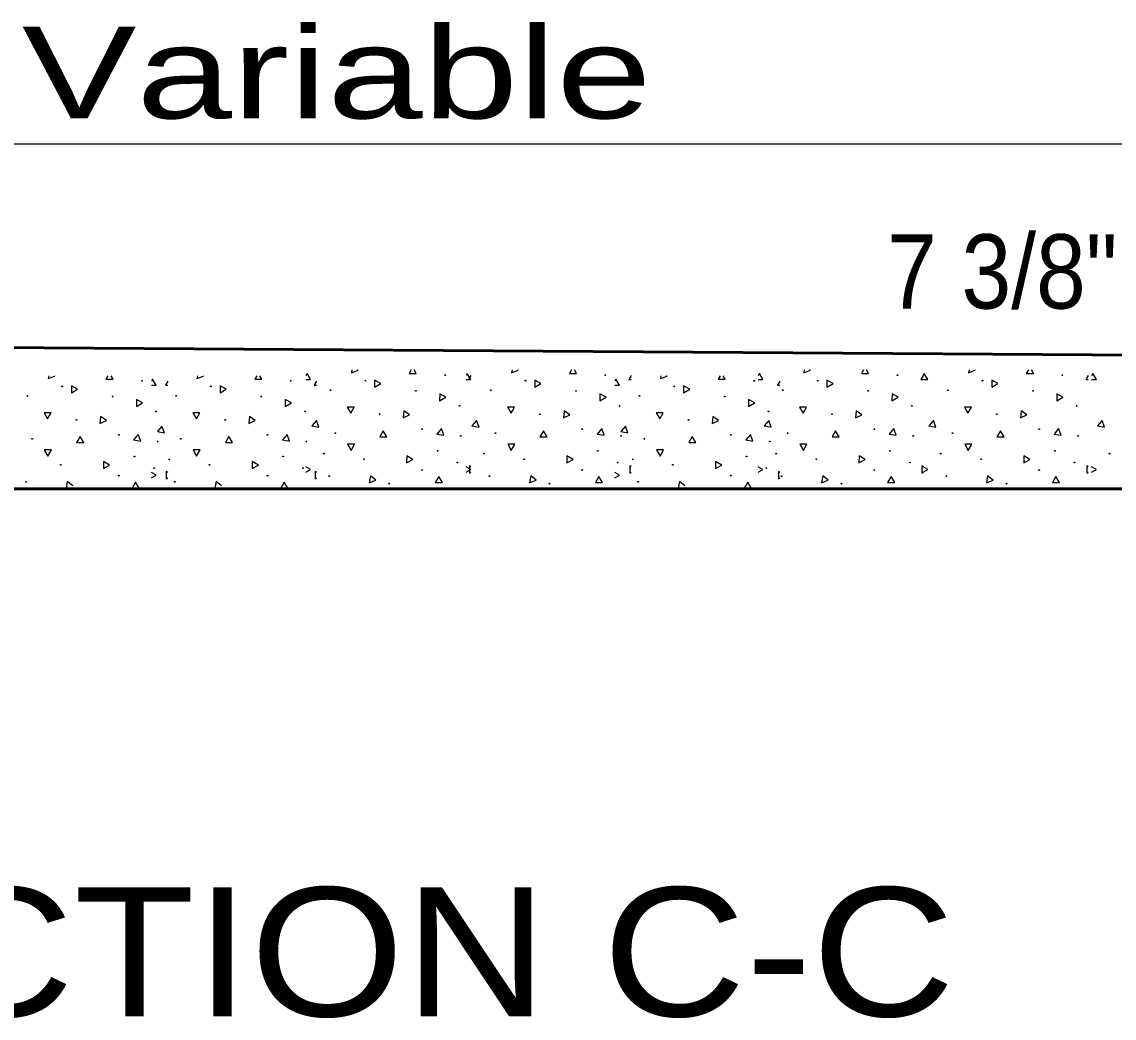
# Model space of a CAD drawing. Extents: x 75.6 to 110.9, y 28 to 50.
# Drawn here: x 100.105 to 101.892, y 35.466 to 37.097 of the extents above; entities that cross this region are included whole.
import ezdxf
from ezdxf.enums import TextEntityAlignment as Align

# ---------------------------------------------------------------- set-up
doc = ezdxf.new("R2010")
doc.units = 0
doc.header["$LTSCALE"] = 0.06
doc.layers.add('1', color=7, linetype='Continuous', lineweight=25)
doc.layers.add('3', color=7, linetype='Continuous', lineweight=13)

msp = doc.modelspace()

# ---------------------------------------------------------------- linework, layer by layer
at = {"layer": '1', "lineweight": 53}
for p, q in [((102.10992, 36.55025), (98.82217, 36.57225)), ((102.13775, 36.33233), (98.82217, 36.33233))]:
    msp.add_line(p, q, dxfattribs=at)
at = {"layer": '1'}
for p, q in [((100.64508, 36.527), (100.64433, 36.52242)), ((100.64433, 36.52242), (100.65525, 36.52642)), ((100.65525, 36.52642), (100.6545, 36.527)), ((100.74208, 36.527), (100.73875, 36.52125)), ((100.75042, 36.52125), (100.74708, 36.527)), ((100.90717, 36.527), (100.90642, 36.52242)), ((100.90642, 36.52242), (100.91733, 36.52642)), ((100.91733, 36.52642), (100.91658, 36.527)), ((101.00417, 36.527), (101.00083, 36.52125)), ((101.0125, 36.52125), (101.00917, 36.527)), ((101.38508, 36.527), (101.38433, 36.52242)), ((101.38433, 36.52242), (101.39525, 36.52642)), ((101.39525, 36.52642), (101.3945, 36.527)), ((101.48208, 36.527), (101.47875, 36.52125)), ((101.49042, 36.52125), (101.48708, 36.527)), ((101.65475, 36.527), (101.654, 36.52242)), ((101.654, 36.52242), (101.66492, 36.52642)), ((101.66492, 36.52642), (101.66417, 36.527)), ((101.75175, 36.527), (101.74842, 36.52125)), ((101.76008, 36.52125), (101.75675, 36.527)), ((100.14908, 36.51767), (100.14833, 36.51308)), ((100.14833, 36.51308), (100.15925, 36.51708)), ((100.15925, 36.51708), (100.1585, 36.51767)), ((100.24608, 36.51767), (100.24275, 36.51192)), ((100.24275, 36.51192), (100.25442, 36.51192)), ((100.25442, 36.51192), (100.25108, 36.51767)), ((100.31908, 36.51208), (100.31717, 36.50883)), ((100.32483, 36.502), (100.31908, 36.51208)), ((100.34383, 36.50883), (100.33992, 36.502)), ((100.39242, 36.51767), (100.39167, 36.51308)), ((100.39167, 36.51308), (100.40258, 36.51708)), ((100.40258, 36.51708), (100.40183, 36.51767)), ((100.48942, 36.51767), (100.48608, 36.51192)), ((100.48608, 36.51192), (100.49775, 36.51192)), ((100.49775, 36.51192), (100.49442, 36.51767)), ((100.57175, 36.52142), (100.56983, 36.51817)), ((100.56983, 36.51133), (100.5775, 36.51133)), ((100.5775, 36.51133), (100.57175, 36.52142)), ((100.58717, 36.50883), (100.58325, 36.502)), ((100.73875, 36.52125), (100.75042, 36.52125)), ((100.83383, 36.52142), (100.83192, 36.51817)), ((100.83192, 36.51133), (100.83958, 36.51133)), ((100.83958, 36.51133), (100.83383, 36.52142)), ((100.83983, 36.51817), (100.83592, 36.51133)), ((100.83592, 36.51133), (100.83983, 36.51133)), ((101.00083, 36.52125), (101.0125, 36.52125)), ((101.07717, 36.51208), (101.07525, 36.50883)), ((101.08292, 36.502), (101.07717, 36.51208)), ((101.10192, 36.51817), (101.098, 36.51133)), ((101.098, 36.51133), (101.10192, 36.51133)), ((101.1505, 36.51767), (101.14975, 36.51308)), ((101.14975, 36.51308), (101.16067, 36.51708)), ((101.16067, 36.51708), (101.15992, 36.51767)), ((101.2475, 36.51767), (101.24417, 36.51192)), ((101.24417, 36.51192), (101.25583, 36.51192)), ((101.25583, 36.51192), (101.2525, 36.51767)), ((101.31175, 36.52142), (101.30983, 36.51817)), ((101.30983, 36.51133), (101.3175, 36.51133)), ((101.3175, 36.51133), (101.31175, 36.52142)), ((101.34525, 36.50883), (101.34133, 36.502)), ((101.47875, 36.52125), (101.49042, 36.52125)), ((101.57983, 36.51817), (101.57592, 36.51133)), ((101.57592, 36.51133), (101.57983, 36.51133)), ((101.58142, 36.52142), (101.5795, 36.51817)), ((101.5795, 36.51133), (101.58717, 36.51133)), ((101.58717, 36.51133), (101.58142, 36.52142)), ((101.74842, 36.52125), (101.76008, 36.52125)), ((101.8495, 36.51817), (101.84558, 36.51133)), ((101.84558, 36.51133), (101.8495, 36.51133)), ((101.85725, 36.52142), (101.85533, 36.51817)), ((101.85533, 36.51133), (101.863, 36.51133)), ((101.863, 36.51133), (101.85725, 36.52142)), ((100.31717, 36.502), (100.32483, 36.502)), ((100.33992, 36.502), (100.34383, 36.502)), ((100.58325, 36.502), (100.58717, 36.502)), ((101.07525, 36.502), (101.08292, 36.502)), ((101.34133, 36.502), (101.34525, 36.502)), ((100.8375, 36.37), (100.8375, 36.35833)), ((100.8375, 36.37), (100.8375, 36.35833)), ((100.83983, 36.36867), (100.8375, 36.37)), ((100.83983, 36.36867), (100.8375, 36.37)), ((101.09958, 36.37), (101.09958, 36.35833)), ((101.09958, 36.37), (101.09958, 36.35833)), ((101.10192, 36.36867), (101.09958, 36.37)), ((101.10192, 36.36867), (101.09958, 36.37)), ((101.5775, 36.37), (101.5775, 36.35833)), ((101.5775, 36.37), (101.5775, 36.35833)), ((101.57983, 36.36867), (101.5775, 36.37)), ((101.57983, 36.36867), (101.5775, 36.37)), ((101.84717, 36.37), (101.84717, 36.35833)), ((101.84717, 36.37), (101.84717, 36.35833)), ((101.8495, 36.36867), (101.84717, 36.37)), ((101.8495, 36.36867), (101.84717, 36.37)), ((100.3415, 36.36067), (100.3415, 36.349)), ((100.3415, 36.36067), (100.3415, 36.349)), ((100.34383, 36.35933), (100.3415, 36.36067)), ((100.34383, 36.35933), (100.3415, 36.36067)), ((100.3415, 36.349), (100.34383, 36.35033)), ((100.3415, 36.349), (100.34383, 36.35033)), ((100.58483, 36.36067), (100.58483, 36.349)), ((100.58483, 36.36067), (100.58483, 36.349)), ((100.58717, 36.35933), (100.58483, 36.36067)), ((100.58717, 36.35933), (100.58483, 36.36067)), ((100.58483, 36.349), (100.58717, 36.35033)), ((100.58483, 36.349), (100.58717, 36.35033)), ((100.8375, 36.35833), (100.83983, 36.35967)), ((100.8375, 36.35833), (100.83983, 36.35967)), ((101.09958, 36.35833), (101.10192, 36.35967)), ((101.09958, 36.35833), (101.10192, 36.35967)), ((101.34292, 36.36067), (101.34292, 36.349)), ((101.34292, 36.36067), (101.34292, 36.349)), ((101.34525, 36.35933), (101.34292, 36.36067)), ((101.34525, 36.35933), (101.34292, 36.36067)), ((101.34292, 36.349), (101.34525, 36.35033)), ((101.34292, 36.349), (101.34525, 36.35033)), ((101.5775, 36.35833), (101.57983, 36.35967)), ((101.5775, 36.35833), (101.57983, 36.35967)), ((101.84717, 36.35833), (101.8495, 36.35967)), ((101.84717, 36.35833), (101.8495, 36.35967))]:
    msp.add_line(p, q, dxfattribs=at)
for points in [[(100.68225, 36.49875), (100.69233, 36.50467), (100.68233, 36.5105)], [(100.94433, 36.49875), (100.95442, 36.50467), (100.94442, 36.5105)], [(101.42225, 36.49875), (101.43233, 36.50467), (101.42233, 36.5105)], [(101.69192, 36.49875), (101.702, 36.50467), (101.692, 36.5105)], [(100.18625, 36.48942), (100.19633, 36.49533), (100.18633, 36.50117)], [(100.42958, 36.48942), (100.43967, 36.49533), (100.42967, 36.50117)], [(101.18767, 36.48942), (101.19775, 36.49533), (101.18775, 36.50117)], [(100.29258, 36.46717), (100.30275, 36.473), (100.29275, 36.47883)], [(100.53592, 36.46717), (100.54608, 36.473), (100.53608, 36.47883)], [(100.78858, 36.4765), (100.79875, 36.48233), (100.78875, 36.48817)], [(101.05067, 36.4765), (101.06083, 36.48233), (101.05083, 36.48817)], [(101.294, 36.46717), (101.30417, 36.473), (101.29417, 36.47883)], [(101.52858, 36.4765), (101.53875, 36.48233), (101.52875, 36.48817)], [(101.79825, 36.4765), (101.80842, 36.48233), (101.79842, 36.48817)], [(100.14733, 36.447), (100.15308, 36.457), (100.1415, 36.457)], [(100.39067, 36.447), (100.39642, 36.457), (100.38483, 36.457)], [(100.64333, 36.45633), (100.64908, 36.46633), (100.6375, 36.46633)], [(100.729, 36.44867), (100.7395, 36.45367), (100.73008, 36.46033)], [(100.90542, 36.45633), (100.91117, 36.46633), (100.89958, 36.46633)], [(100.99108, 36.44867), (101.00158, 36.45367), (100.99217, 36.46033)], [(101.14875, 36.447), (101.1545, 36.457), (101.14292, 36.457)], [(101.38333, 36.45633), (101.38908, 36.46633), (101.3775, 36.46633)], [(101.469, 36.44867), (101.4795, 36.45367), (101.47008, 36.46033)], [(101.653, 36.45633), (101.65875, 36.46633), (101.64717, 36.46633)], [(101.73867, 36.44867), (101.74917, 36.45367), (101.73975, 36.46033)], [(100.233, 36.43933), (100.2435, 36.44433), (100.23408, 36.451)], [(100.47633, 36.43933), (100.48683, 36.44433), (100.47742, 36.451)], [(100.5795, 36.4355), (100.591, 36.4335), (100.58708, 36.44433)], [(100.84158, 36.4355), (100.85308, 36.4335), (100.84917, 36.44433)], [(101.23442, 36.43933), (101.24492, 36.44433), (101.2355, 36.451)], [(101.3195, 36.4355), (101.331, 36.4335), (101.32708, 36.44433)], [(101.58917, 36.4355), (101.60067, 36.4335), (101.59675, 36.44433)], [(101.865, 36.4355), (101.8765, 36.4335), (101.87258, 36.44433)], [(100.19475, 36.40808), (100.20633, 36.40808), (100.2005, 36.41817)], [(100.28808, 36.41275), (100.29958, 36.41075), (100.29567, 36.42167)], [(100.32683, 36.42617), (100.33833, 36.42417), (100.33442, 36.435)], [(100.43808, 36.40808), (100.44967, 36.40808), (100.44383, 36.41817)], [(100.53142, 36.41275), (100.54292, 36.41075), (100.539, 36.42167)], [(100.69075, 36.41742), (100.70233, 36.41742), (100.6965, 36.4275)], [(100.78408, 36.42208), (100.79558, 36.42008), (100.79167, 36.431)], [(100.95283, 36.41742), (100.96442, 36.41742), (100.95858, 36.4275)], [(101.04617, 36.42208), (101.05767, 36.42008), (101.05375, 36.431)], [(101.08492, 36.42617), (101.09642, 36.42417), (101.0925, 36.435)], [(101.19617, 36.40808), (101.20775, 36.40808), (101.20192, 36.41817)], [(101.2895, 36.41275), (101.301, 36.41075), (101.29708, 36.42167)], [(101.43075, 36.41742), (101.44233, 36.41742), (101.4365, 36.4275)], [(101.52408, 36.42208), (101.53558, 36.42008), (101.53167, 36.431)], [(101.70042, 36.41742), (101.712, 36.41742), (101.70617, 36.4275)], [(101.79375, 36.42208), (101.80525, 36.42008), (101.80133, 36.431)], [(100.64375, 36.39542), (100.64958, 36.4055), (100.63792, 36.4055)], [(100.90583, 36.39542), (100.91167, 36.4055), (100.9, 36.4055)], [(101.38375, 36.39542), (101.38958, 36.4055), (101.37792, 36.4055)], [(101.65342, 36.39542), (101.65925, 36.4055), (101.64758, 36.4055)], [(100.14775, 36.38608), (100.15358, 36.39617), (100.14192, 36.39617)], [(100.39108, 36.38608), (100.39692, 36.39617), (100.38525, 36.39617)], [(100.73467, 36.37492), (100.74475, 36.38067), (100.73475, 36.3865)], [(100.99675, 36.37492), (101.00683, 36.38067), (100.99683, 36.3865)], [(101.14917, 36.38608), (101.155, 36.39617), (101.14333, 36.39617)], [(101.47467, 36.37492), (101.48475, 36.38067), (101.47475, 36.3865)], [(101.74433, 36.37492), (101.75442, 36.38067), (101.74442, 36.3865)], [(100.23867, 36.36558), (100.24875, 36.37133), (100.23875, 36.37717)], [(100.482, 36.36558), (100.49208, 36.37133), (100.48208, 36.37717)], [(101.24008, 36.36558), (101.25017, 36.37133), (101.24017, 36.37717)], [(100.6735, 36.3425), (100.68442, 36.3465), (100.6755, 36.354)], [(100.78142, 36.34283), (100.79308, 36.34283), (100.78725, 36.35292)], [(100.93558, 36.3425), (100.9465, 36.3465), (100.93758, 36.354)], [(101.0435, 36.34283), (101.05517, 36.34283), (101.04933, 36.35292)], [(101.4135, 36.3425), (101.42442, 36.3465), (101.4155, 36.354)], [(101.52142, 36.34283), (101.53308, 36.34283), (101.52725, 36.35292)], [(101.68317, 36.3425), (101.69408, 36.3465), (101.68517, 36.354)], [(101.79108, 36.34283), (101.80275, 36.34283), (101.79692, 36.35292)]]:
    msp.add_lwpolyline(points, close=True, dxfattribs=at)
for points in [[(100.56983, 36.35967), (100.57758, 36.36417), (100.56983, 36.36867)], [(100.83192, 36.35967), (100.83967, 36.36417), (100.83192, 36.36867)], [(101.30983, 36.35967), (101.31758, 36.36417), (101.30983, 36.36867)], [(101.5795, 36.35967), (101.58725, 36.36417), (101.5795, 36.36867)], [(101.85533, 36.35967), (101.86308, 36.36417), (101.85533, 36.36867)], [(100.31717, 36.35033), (100.32492, 36.35483), (100.31717, 36.35933)], [(101.07525, 36.35033), (101.083, 36.35483), (101.07525, 36.35933)], [(100.18842, 36.33717), (100.1795, 36.34467), (100.1775, 36.33317)], [(100.29708, 36.3335), (100.29125, 36.34358), (100.28542, 36.3335)], [(100.43175, 36.33717), (100.42283, 36.34467), (100.42083, 36.33317)], [(100.54042, 36.3335), (100.53458, 36.34358), (100.52875, 36.3335)], [(101.18983, 36.33717), (101.18092, 36.34467), (101.17892, 36.33317)], [(101.2985, 36.3335), (101.29267, 36.34358), (101.28683, 36.3335)]]:
    msp.add_lwpolyline(points, dxfattribs=at)
for centre in [(100.30165, 36.50908), (100.54498, 36.50908), (100.66712, 36.50948), (100.79765, 36.51842), (100.92921, 36.50948), (101.05973, 36.51842), (101.30306, 36.50908), (101.40712, 36.50948), (101.53765, 36.51842), (101.67679, 36.50948), (101.80731, 36.51842), (100.17112, 36.50015), (100.41446, 36.50015), (100.61022, 36.49387), (100.74968, 36.49277), (100.8723, 36.49387), (101.01176, 36.49277), (101.17254, 36.50015), (101.35022, 36.49387), (101.48968, 36.49277), (101.61989, 36.49387), (101.75934, 36.49277), (100.11422, 36.48454), (100.25368, 36.48343), (100.35755, 36.48454), (100.49701, 36.48343), (101.11564, 36.48454), (101.25509, 36.48343), (100.32509, 36.45889), (100.56842, 36.45889), (100.69055, 36.45483), (100.82109, 36.46822), (100.95263, 36.45483), (101.08317, 36.46822), (101.32651, 36.45889), (101.43055, 36.45483), (101.56109, 36.46822), (101.70021, 36.45483), (101.83076, 36.46822), (100.19455, 36.4455), (100.43788, 36.4455), (101.19596, 36.4455), (100.26373, 36.42095), (100.50707, 36.42095), (100.61805, 36.42358), (100.75973, 36.43028), (100.82332, 36.41912), (100.88013, 36.42358), (101.02182, 36.43028), (101.0854, 36.41912), (101.26515, 36.42095), (101.35805, 36.42358), (101.49973, 36.43028), (101.56332, 36.41912), (101.62772, 36.42358), (101.7694, 36.43028), (101.83298, 36.41912), (100.12205, 36.41425), (100.32732, 36.40979), (100.36538, 36.41425), (100.57065, 36.40979), (101.12347, 36.41425), (101.32873, 36.40979), (100.28938, 36.38524), (100.53272, 36.38524), (100.59908, 36.39012), (100.78538, 36.39458), (100.86117, 36.39012), (101.04747, 36.39458), (101.2908, 36.38524), (101.33908, 36.39012), (101.52538, 36.39458), (101.60875, 36.39012), (101.79505, 36.39458), (101.88458, 36.39012), (100.1689, 36.37186), (100.32174, 36.36628), (100.34642, 36.38079), (100.41223, 36.37186), (100.56507, 36.36628), (100.6649, 36.38119), (100.81774, 36.37561), (100.92698, 36.38119), (101.07982, 36.37561), (101.1045, 36.38079), (101.17031, 36.37186), (101.32315, 36.36628), (101.4049, 36.38119), (101.55774, 36.37561), (101.67456, 36.38119), (101.8274, 36.37561), (100.26373, 36.35401), (100.50707, 36.35401), (100.60799, 36.35331), (100.75973, 36.36335), (100.87008, 36.35331), (101.02182, 36.36335), (101.26515, 36.35401), (101.34799, 36.35331), (101.49973, 36.36335), (101.61766, 36.35331), (101.7694, 36.36335), (100.11199, 36.34398), (100.35533, 36.34398), (100.70618, 36.34103), (100.96827, 36.34103), (101.11341, 36.34398), (101.44618, 36.34103), (101.71585, 36.34103)]:
    msp.add_circle(centre, 0.000647, dxfattribs=at)
at = {"layer": '3', "lineweight": 25}
msp.add_line((102.41458, 36.89625), (98.84517, 36.89625), dxfattribs=at)

# ---------------------------------------------------------------- texts
at = {"layer": '1'}
for s, height, width, p in [('Variable', 0.15, 1.4, (100.62054, 36.93867)), ('7 3/8"', 0.1215, 0.9, (101.70904, 36.6275)), ('SECTION C-C', 0.2109, 1.15, (100.57754, 35.46933))]:
    msp.add_text(s, height=height, dxfattribs=dict(at, width=width)).set_placement(p, align=Align.CENTER)

doc.saveas('drawing.dxf')
